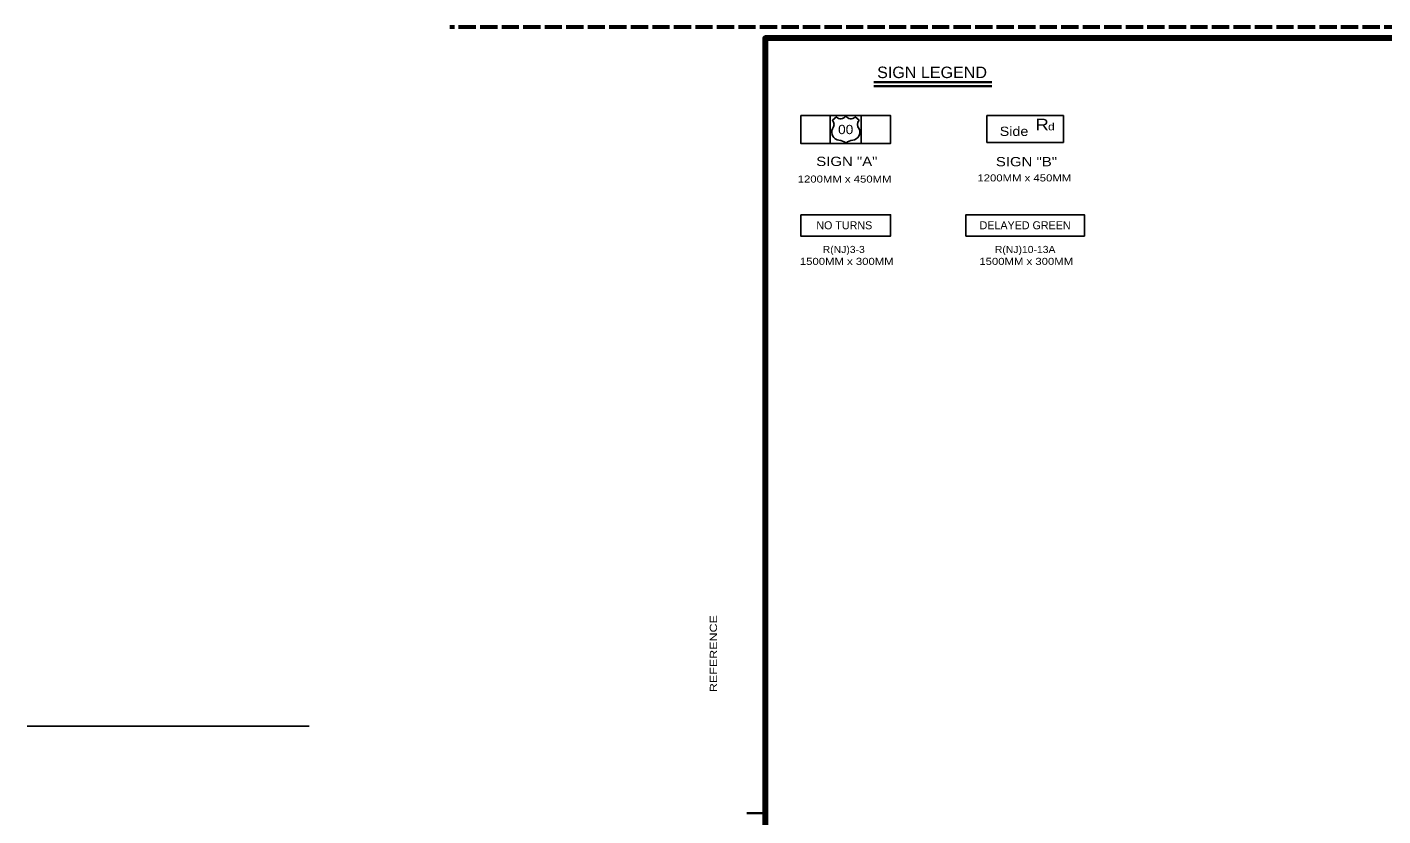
# Model space of a CAD drawing. Extents: x 168203 to 169864, y 223196 to 223870.
# Drawn here: x 169051.6 to 169193.4, y 223617 to 223699.4 of the extents above; entities that cross this region are included whole.
import ezdxf
from ezdxf.enums import TextEntityAlignment as Align

# ---------------------------------------------------------------- set-up
doc = ezdxf.new("R2010")
doc.units = 0
doc.header["$LTSCALE"] = 0.3
doc.linetypes.add('LONG_DASHED', pattern=[7.5, 6, -1.5])
doc.layers.add('1', color=7, linetype='Continuous', lineweight=13)
doc.layers.add('10', color=7, linetype='Continuous', lineweight=13)

msp = doc.modelspace()

# ---------------------------------------------------------------- linework, layer by layer
at = {"layer": '1', "linetype": 'LONG_DASHED', "lineweight": 60}
msp.add_line((169364.0333, 223699.3889), (169095.8093, 223699.3889), dxfattribs=at)
at = {"layer": '1', "lineweight": 25}
msp.add_line((169051.6157, 223626.3628), (169081.1031, 223626.3628), dxfattribs=at)
at = {"layer": '1', "lineweight": 35}
msp.add_line((169126.8633, 223617.2489), (169128.7833, 223617.2489), dxfattribs=at)
at = {"layer": '1', "lineweight": 158}
msp.add_lwpolyline([(169361.2833, 223536.2489), (169361.2833, 223698.2489), (169128.7833, 223698.2489), (169128.7833, 223536.2489)], close=True, dxfattribs=at)
at = {"layer": '10', "lineweight": 35}
for p, q in [((169140.1244, 223693.6356), (169152.4724, 223693.6356)), ((169140.1244, 223693.2254), (169152.4724, 223693.2254))]:
    msp.add_line(p, q, dxfattribs=at)
at = {"layer": '10', "lineweight": 25}
for p, q in [((169136.226, 223689.9997), (169135.816, 223689.6717)), ((169138.1943, 223689.9997), (169138.616, 223689.6717))]:
    msp.add_line(p, q, dxfattribs=at)
at = {"layer": '10'}
for p, q in [((169136.226, 223689.9997), (169135.816, 223689.6717)), ((169138.616, 223689.6717), (169138.1943, 223689.9997)), ((169137.1968, 223687.2927), (169137.1968, 223687.2348)), ((169137.2102, 223687.2348), (169137.2102, 223687.2817))]:
    msp.add_line(p, q, dxfattribs=at)
at = {"layer": '10', "lineweight": 25}
for points in [[(169132.5004, 223690.152), (169141.8964, 223690.152), (169141.8964, 223687.2348), (169132.5004, 223687.2348)], [(169138.8152, 223690.152), (169135.5817, 223690.152), (169135.5817, 223687.2348), (169138.8152, 223687.2348)], [(169151.9695, 223690.152), (169159.9596, 223690.152), (169159.9596, 223687.3402), (169151.9695, 223687.3402)], [(169132.5004, 223679.7883), (169141.8964, 223679.7883), (169141.8964, 223677.5563), (169132.5004, 223677.5563)], [(169149.7677, 223677.5563), (169149.7677, 223679.7883), (169162.1637, 223679.7883), (169162.1637, 223677.5563)]]:
    msp.add_lwpolyline(points, close=True, dxfattribs=at)
at = {"layer": '10'}
for points in [[(169137.1968, 223687.2348), (169135.5817, 223687.2348), (169135.5817, 223690.152)], [(169135.5817, 223690.152), (169138.8152, 223690.152), (169138.8152, 223687.2348), (169137.2102, 223687.2348)]]:
    msp.add_lwpolyline(points, dxfattribs=at)
at = {"layer": '10', "lineweight": 25}
for centre, radius, start, end in [((169135.2885, 223689.2177), 0.6915, 318.96758, 41.03242), ((169136.6771, 223690.4691), 0.6509, 226.13784, 324.97605), ((169137.7432, 223690.4691), 0.6509, 215.02395, 313.86216), ((169139.1318, 223689.2177), 0.6915, 138.96758, 221.03243), ((169136.5841, 223688.4209), 0.8464, 156.10933, 263.19699), ((169137.8363, 223688.4209), 0.8464, 276.80301, 23.89067), ((169136.3784, 223686.2918), 1.2929, 49.96097, 85.32525), ((169138.0419, 223686.2918), 1.2929, 94.67475, 130.03903)]:
    msp.add_arc(centre, radius, start, end, dxfattribs=at)
at = {"layer": '10'}
for centre, radius, start, end in [((169135.2885, 223689.2177), 0.6915, 318.96758, 41.03242), ((169136.6771, 223690.4691), 0.6509, 226.13784, 324.97605), ((169137.7432, 223690.4691), 0.6509, 215.02395, 313.86216), ((169139.1318, 223689.2177), 0.6915, 138.96758, 221.03243), ((169136.5841, 223688.4209), 0.8464, 156.10933, 263.19699), ((169137.8363, 223688.4209), 0.8464, 276.80301, 23.89067), ((169136.3784, 223686.2918), 1.2929, 50.72986, 85.32525), ((169138.0419, 223686.2918), 1.2929, 94.67475, 130.03661)]:
    msp.add_arc(centre, radius, start, end, dxfattribs=at)

# ---------------------------------------------------------------- texts
at = {"layer": '1', "width": 1.3}
msp.add_text('REFERENCE                                                              ', height=0.75, rotation=90, dxfattribs=at).set_placement((169123.7433, 223629.9089))
at = {"layer": '10'}
for s, height, width, p in [('SIGN LEGEND', 1.197, 1.05, (169146.23, 223694.0654)), (' R', 1.215, 1.2, (169157.4684, 223688.6016)), (' d', 0.7779, 1.2, (169158.529, 223688.6016)), ('00', 0.9724, 1.1, (169137.1985, 223688.2072)), ('Side', 0.9724, 1.15, (169154.7992, 223688.0197))]:
    msp.add_text(s, height=height, dxfattribs=dict(at, width=width)).set_placement(p, align=Align.CENTER)
for s, height, width, p in [('SIGN "A"', 0.9724, 1.2, (169134.1218, 223684.8753)), ('SIGN "B"', 0.9724, 1.2, (169152.9025, 223684.848)), ('1200MM x 450MM', 0.738, 1.2, (169132.1826, 223683.1471)), ('1200MM x 450MM', 0.738, 1.2, (169150.9715, 223683.2639)), ('1500MM x 300MM', 0.738, 1.2, (169132.4055, 223674.5461)), ('R(NJ)3-3', 0.738, 1.1, (169134.7954, 223675.7923)), ('1500MM x 300MM', 0.738, 1.2, (169151.1728, 223674.5461)), ('R(NJ)10-13A', 0.738, 1.1, (169152.7948, 223675.7923))]:
    msp.add_text(s, height=height, dxfattribs=dict(at, width=width)).set_placement(p)
for s, p in [('NO TURNS', (169134.1294, 223678.2673)), ('DELAYED GREEN', (169151.1989, 223678.2673))]:
    msp.add_text(s, height=0.837, dxfattribs=at).set_placement(p)

doc.saveas('drawing.dxf')
